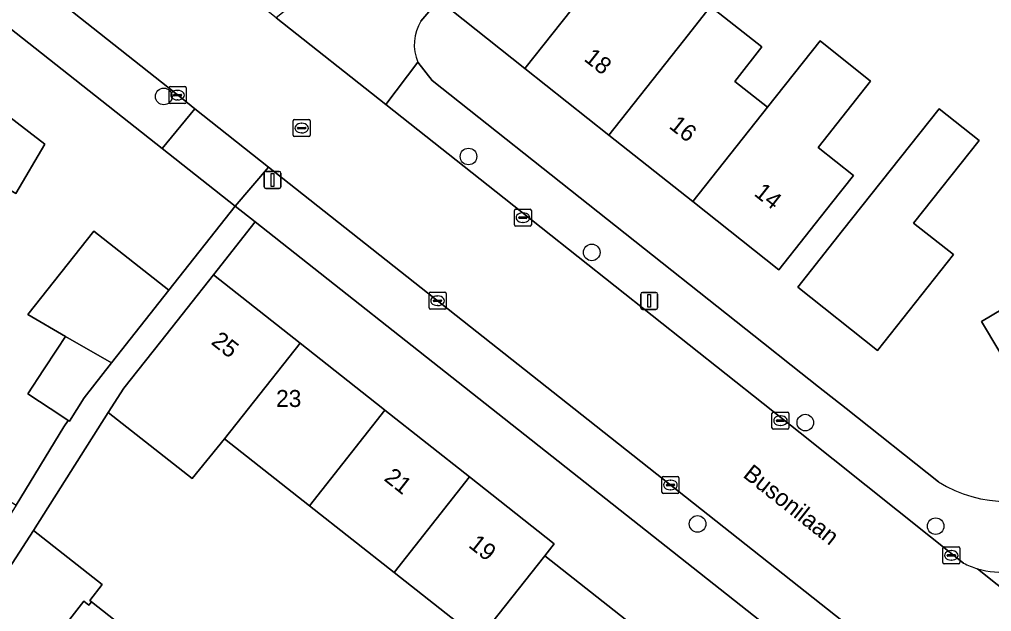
# Model space of a CAD drawing. Extents: x 159217 to 160349, y 381246 to 382172.
# Drawn here: x 160138.1 to 160195.3, y 381988.1 to 382022.9 of the extents above; entities that cross this region are included whole.
import ezdxf

# ---------------------------------------------------------------- set-up
doc = ezdxf.new("R2010")
doc.units = 0
for name, color, linetype in [('IMGEO_Boom', 7, 'Continuous'), ('IMGEO_Erf', 7, 'Continuous'), ('IMGEO_Kolk', 7, 'Continuous'), ('IMGEO_Lichtmast', 7, 'Continuous'), ('IMGEO_Muur', 7, 'Continuous'), ('IMGEO_Openbare_ruimte_label', 7, 'Continuous'), ('IMGEO_Pand', 7, 'Continuous'), ('IMGEO_Pand_nummerreeks', 7, 'Continuous'), ('IMGEO_Rijbaan_lokaal_open', 7, 'Continuous'), ('IMGEO_Rioolput', 7, 'Continuous'), ('IMGEO_Voetpad_open', 7, 'Continuous')]:
    doc.layers.add(name, color=color, linetype=linetype)

msp = doc.modelspace()

# ---------------------------------------------------------------- linework, layer by layer
at = {"layer": 'IMGEO_Boom'}
for centre in [(160146.591, 382018.373), (160164.533, 382014.84), (160171.786, 382009.194), (160184.362, 381999.177), (160178.018, 381993.215), (160192.036, 381993.082)]:
    msp.add_circle(centre, 0.489, dxfattribs=at)
at = {"layer": 'IMGEO_Erf'}
for points in [[(160135.459, 381995.859), (160137.912, 381994.317), (160140.717, 381998.927), (160140.962, 381999.311), (160140.583, 381999.559), (160138.586, 382000.866), (160139.517, 382002.28), (160140.314, 382003.49), (160140.816, 382004.253), (160138.582, 382005.534), (160142.466, 382010.454), (160146.885, 382006.965), (160150.798, 382011.919), (160146.492, 382015.319), (160130.774, 382027.732)], [(160178.788, 382023.674), (160181.806, 382021.284), (160180.205, 382019.262), (160182.135, 382017.733), (160185.23, 382021.639), (160188.206, 382019.282), (160185.111, 382015.376), (160187.203, 382013.719), (160185.91, 382012.087), (160182.805, 382008.168), (160177.738, 382012.183), (160172.79, 382016.103), (160167.842, 382020.023), (160162.777, 382024.035), (160161.732, 382022.812)], [(160233.929, 382018.543), (160233.082, 382019.946), (160225.46, 382015.406), (160220.047, 382012.182), (160214.635, 382008.958), (160209.222, 382005.734), (160203.81, 382002.51), (160199.595, 382000), (160198.272, 381999.212), (160197.801, 382000), (160194.739, 382005.121), (160199.034, 382007.682), (160200.285, 382008.428), (160199.136, 382010.356), (160199.038, 382010.521), (160198.981, 382010.617), (160204.393, 382013.84), (160207.546, 382015.718), (160208.848, 382013.532), (160211.108, 382014.879), (160209.911, 382016.888), (160215.324, 382020.112), (160216.519, 382018.105), (160221.931, 382021.33)], [(160161.552, 382020.389), (160162.394, 382019.303), (160181.902, 382003.848), (160183.535, 382002.554), (160185.145, 382001.278), (160186.758, 382000), (160192.196, 381995.692)], [(160164.507, 381986.918), (160160.15, 381990.354), (160155.165, 381994.285), (160150.177, 381998.219), (160148.267, 381995.88), (160143.327, 381999.776), (160138.933, 381992.828), (160142.971, 381989.64), (160142.24, 381988.714), (160142.347, 381988.629), (160147.34, 381984.688)]]:
    msp.add_lwpolyline(points, dxfattribs=at)
for points in [[(160118.255, 381987.024), (160117.408, 381985.582), (160114.88, 381981.268), (160107.512, 381985.605), (160110.881, 381991.35), (160114.176, 381996.967), (160115.955, 382000), (160117.471, 382002.584), (160120.765, 382008.2), (160124.08, 382013.852), (160127.432, 382019.567), (160131.914, 382016.929), (160133.752, 382020.052), (160139.591, 382015.557), (160137.882, 382012.653), (160134.482, 382014.654), (160131.509, 382009.591), (160128.149, 382003.87), (160125.876, 382000), (160124.851, 381998.255), (160121.553, 381992.64)], [(160194.59, 382015.784), (160190.739, 382010.925), (160193.088, 382009.064), (160188.616, 382003.421), (160183.914, 382007.147), (160186.553, 382010.478), (160192.236, 382017.65)], [(160165.891, 382000), (160151.974, 382010.99), (160149.511, 382007.871), (160154.615, 382003.845), (160159.491, 382000), (160159.601, 381999.913), (160164.588, 381995.98), (160169.581, 381992.043), (160169.028, 381991.343), (160174.123, 381987.314), (160179.51, 381983.054), (160182.521, 381986.867)]]:
    msp.add_lwpolyline(points, close=True, dxfattribs=at)
for centre, radius, start, end in [((160164, 382021.425), 2.659, 148.5615, 202.9414), ((160196.232, 382002.153), 7.618, 238.008, 302.3452)]:
    msp.add_arc(centre, radius, start, end, dxfattribs=at)
at = {"layer": 'IMGEO_Kolk'}
for p, q in [((160146.904, 382018.026), (160146.904, 382018.878)), ((160146.979, 382018.952), (160147.831, 382018.952)), ((160147.392, 382018.732), (160147.417, 382018.732)), ((160147.905, 382018.878), (160147.905, 382018.026)), ((160147.163, 382018.446), (160147.163, 382018.458)), ((160147.601, 382018.409), (160147.203, 382018.409)), ((160147.206, 382018.495), (160147.604, 382018.495)), ((160147.415, 382018.172), (160147.39, 382018.172)), ((160147.647, 382018.458), (160147.647, 382018.446)), ((160147.831, 382017.952), (160146.979, 382017.952)), ((160167.233, 382010.816), (160167.233, 382011.668)), ((160167.308, 382011.742), (160168.16, 382011.742)), ((160168.234, 382011.668), (160168.234, 382010.816)), ((160167.492, 382011.236), (160167.492, 382011.248)), ((160167.93, 382011.199), (160167.532, 382011.199)), ((160167.535, 382011.285), (160167.933, 382011.285)), ((160167.721, 382011.522), (160167.746, 382011.522)), ((160167.976, 382011.248), (160167.976, 382011.236)), ((160168.16, 382010.742), (160167.308, 382010.742)), ((160167.744, 382010.962), (160167.719, 382010.962)), ((160162.21, 382005.923), (160162.21, 382006.775)), ((160162.285, 382006.849), (160163.137, 382006.849)), ((160162.698, 382006.629), (160162.723, 382006.629)), ((160163.211, 382006.775), (160163.211, 382005.923)), ((160162.469, 382006.343), (160162.469, 382006.355)), ((160162.907, 382006.306), (160162.509, 382006.306)), ((160162.512, 382006.392), (160162.91, 382006.392)), ((160162.721, 382006.069), (160162.696, 382006.069)), ((160162.953, 382006.355), (160162.953, 382006.343)), ((160163.137, 382005.849), (160162.285, 382005.849)), ((160182.399, 381998.864), (160182.399, 381999.716)), ((160182.474, 381999.79), (160183.326, 381999.79)), ((160183.4, 381999.716), (160183.4, 381998.864)), ((160182.658, 381999.284), (160182.658, 381999.296)), ((160183.096, 381999.247), (160182.698, 381999.247)), ((160182.701, 381999.333), (160183.099, 381999.333)), ((160182.887, 381999.57), (160182.912, 381999.57)), ((160183.142, 381999.296), (160183.142, 381999.284)), ((160183.326, 381998.79), (160182.474, 381998.79)), ((160182.91, 381999.01), (160182.885, 381999.01)), ((160175.922, 381995.079), (160175.922, 381995.931)), ((160175.997, 381996.005), (160176.849, 381996.005)), ((160176.41, 381995.785), (160176.435, 381995.785)), ((160176.923, 381995.931), (160176.923, 381995.079)), ((160176.181, 381995.499), (160176.181, 381995.511)), ((160176.619, 381995.462), (160176.221, 381995.462)), ((160176.224, 381995.548), (160176.622, 381995.548)), ((160176.433, 381995.225), (160176.408, 381995.225)), ((160176.665, 381995.511), (160176.665, 381995.499)), ((160176.849, 381995.005), (160175.997, 381995.005)), ((160192.458, 381990.936), (160192.458, 381991.788)), ((160192.533, 381991.862), (160193.385, 381991.862)), ((160192.946, 381991.642), (160192.971, 381991.642)), ((160193.459, 381991.788), (160193.459, 381990.936)), ((160192.717, 381991.356), (160192.717, 381991.368)), ((160193.155, 381991.319), (160192.757, 381991.319)), ((160192.76, 381991.405), (160193.158, 381991.405)), ((160192.969, 381991.082), (160192.944, 381991.082)), ((160193.201, 381991.368), (160193.201, 381991.356)), ((160193.385, 381990.862), (160192.533, 381990.862))]:
    msp.add_line(p, q, dxfattribs=at)
for points in [[(160146.904, 382018.026), (160146.904, 382018.878)], [(160146.979, 382018.952), (160147.831, 382018.952)], [(160147.905, 382018.878), (160147.905, 382018.026)], [(160147.831, 382017.952), (160146.979, 382017.952)], [(160167.233, 382010.816), (160167.233, 382011.668)], [(160167.308, 382011.742), (160168.16, 382011.742)], [(160168.234, 382011.668), (160168.234, 382010.816)], [(160168.16, 382010.742), (160167.308, 382010.742)], [(160162.21, 382005.923), (160162.21, 382006.775)], [(160162.285, 382006.849), (160163.137, 382006.849)], [(160163.211, 382006.775), (160163.211, 382005.923)], [(160163.137, 382005.849), (160162.285, 382005.849)], [(160182.399, 381998.864), (160182.399, 381999.716)], [(160182.474, 381999.79), (160183.326, 381999.79)], [(160183.4, 381999.716), (160183.4, 381998.864)], [(160183.326, 381998.79), (160182.474, 381998.79)], [(160175.922, 381995.079), (160175.922, 381995.931)], [(160175.997, 381996.005), (160176.849, 381996.005)], [(160176.923, 381995.931), (160176.923, 381995.079)], [(160176.849, 381995.005), (160175.997, 381995.005)], [(160192.458, 381990.936), (160192.458, 381991.788)], [(160192.533, 381991.862), (160193.385, 381991.862)], [(160193.459, 381991.788), (160193.459, 381990.936)], [(160193.385, 381990.862), (160192.533, 381990.862)]]:
    msp.add_lwpolyline(points, dxfattribs=at)
for centre, radius, start, end in [((160146.981, 382018.876), 0.0765, 91.552, 178.448), ((160146.981, 382018.876), 0.0765, 91.552, 178.448), ((160147.829, 382018.876), 0.0765, 1.552, 88.448), ((160147.829, 382018.876), 0.0765, 1.552, 88.448), ((160146.981, 382018.028), 0.0765, 181.552, 268.448), ((160146.981, 382018.028), 0.0765, 181.552, 268.448), ((160147.203, 382018.455), 0.0403, 85.8775, 175.7526), ((160147.2, 382018.445), 0.0366, 178.938, 274.7102), ((160147.604, 382018.452), 0.043, 264.8664, 352.4533), ((160147.608, 382018.457), 0.0386, 1.7309, 96.639), ((160147.829, 382018.028), 0.0765, 271.552, 358.448), ((160147.829, 382018.028), 0.0765, 271.552, 358.448), ((160167.31, 382011.666), 0.0765, 91.552, 178.448), ((160167.31, 382011.666), 0.0765, 91.552, 178.448), ((160168.158, 382011.666), 0.0765, 1.552, 88.448), ((160168.158, 382011.666), 0.0765, 1.552, 88.448), ((160167.532, 382011.245), 0.0403, 85.8775, 175.7526), ((160167.529, 382011.235), 0.0366, 178.938, 274.7102), ((160167.933, 382011.242), 0.043, 264.8664, 352.4533), ((160167.937, 382011.247), 0.0386, 1.7309, 96.639), ((160167.31, 382010.818), 0.0765, 181.552, 268.448), ((160167.31, 382010.818), 0.0765, 181.552, 268.448), ((160168.158, 382010.818), 0.0765, 271.552, 358.448), ((160168.158, 382010.818), 0.0765, 271.552, 358.448), ((160162.287, 382006.773), 0.0765, 91.552, 178.448), ((160162.287, 382006.773), 0.0765, 91.552, 178.448), ((160163.135, 382006.773), 0.0765, 1.552, 88.448), ((160163.135, 382006.773), 0.0765, 1.552, 88.448), ((160162.509, 382006.352), 0.0403, 85.8775, 175.7526), ((160162.506, 382006.342), 0.0366, 178.938, 274.7102), ((160162.91, 382006.349), 0.043, 264.8664, 352.4533), ((160162.914, 382006.354), 0.0386, 1.7309, 96.639), ((160162.287, 382005.925), 0.0765, 181.552, 268.448), ((160162.287, 382005.925), 0.0765, 181.552, 268.448), ((160163.135, 382005.925), 0.0765, 271.552, 358.448), ((160163.135, 382005.925), 0.0765, 271.552, 358.448), ((160182.476, 381999.714), 0.0765, 91.552, 178.448), ((160182.476, 381999.714), 0.0765, 91.552, 178.448), ((160183.324, 381999.714), 0.0765, 1.552, 88.448), ((160183.324, 381999.714), 0.0765, 1.552, 88.448), ((160182.698, 381999.293), 0.0403, 85.8775, 175.7526), ((160182.695, 381999.283), 0.0366, 178.938, 274.7102), ((160183.099, 381999.29), 0.043, 264.8664, 352.4533), ((160183.103, 381999.295), 0.0386, 1.7309, 96.639), ((160182.476, 381998.866), 0.0765, 181.552, 268.448), ((160182.476, 381998.866), 0.0765, 181.552, 268.448), ((160183.324, 381998.866), 0.0765, 271.552, 358.448), ((160183.324, 381998.866), 0.0765, 271.552, 358.448), ((160175.999, 381995.929), 0.0765, 91.552, 178.448), ((160175.999, 381995.929), 0.0765, 91.552, 178.448), ((160176.847, 381995.929), 0.0765, 1.552, 88.448), ((160176.847, 381995.929), 0.0765, 1.552, 88.448), ((160175.999, 381995.081), 0.0765, 181.552, 268.448), ((160175.999, 381995.081), 0.0765, 181.552, 268.448), ((160176.221, 381995.508), 0.0403, 85.8775, 175.7526), ((160176.218, 381995.498), 0.0366, 178.938, 274.7102), ((160176.622, 381995.505), 0.043, 264.8664, 352.4533), ((160176.626, 381995.51), 0.0386, 1.7309, 96.639), ((160176.847, 381995.081), 0.0765, 271.552, 358.448), ((160176.847, 381995.081), 0.0765, 271.552, 358.448), ((160192.535, 381991.786), 0.0765, 91.552, 178.448), ((160192.535, 381991.786), 0.0765, 91.552, 178.448), ((160193.383, 381991.786), 0.0765, 1.552, 88.448), ((160193.383, 381991.786), 0.0765, 1.552, 88.448), ((160192.757, 381991.365), 0.0403, 85.8775, 175.7526), ((160192.754, 381991.355), 0.0366, 178.938, 274.7102), ((160193.158, 381991.362), 0.043, 264.8664, 352.4533), ((160193.162, 381991.367), 0.0386, 1.7309, 96.639), ((160192.535, 381990.938), 0.0765, 181.552, 268.448), ((160192.535, 381990.938), 0.0765, 181.552, 268.448), ((160193.383, 381990.938), 0.0765, 271.552, 358.448), ((160193.383, 381990.938), 0.0765, 271.552, 358.448)]:
    msp.add_arc(centre, radius, start, end, dxfattribs=at)
for centre, major_axis, ratio, start_param, end_param in [((160147.391, 382018.452), (-0.387, 0.002), 0.722429, 4.712389, 7.853982), ((160147.416, 382018.452), (-0.39, 0.002), 0.717154, 1.570796, 4.712389), ((160167.72, 382011.242), (-0.387, 0.002), 0.722429, 4.712389, 7.853982), ((160167.745, 382011.242), (-0.39, 0.002), 0.717154, 1.570796, 4.712389), ((160162.697, 382006.349), (-0.387, 0.002), 0.722429, 4.712389, 7.853982), ((160162.722, 382006.349), (-0.39, 0.002), 0.717154, 1.570796, 4.712389), ((160182.886, 381999.29), (-0.387, 0.002), 0.722429, 4.712389, 7.853982), ((160182.911, 381999.29), (-0.39, 0.002), 0.717154, 1.570796, 4.712389), ((160176.409, 381995.505), (-0.387, 0.002), 0.722429, 4.712389, 7.853982), ((160176.434, 381995.505), (-0.39, 0.002), 0.717154, 1.570796, 4.712389), ((160192.945, 381991.362), (-0.387, 0.002), 0.722429, 4.712389, 7.853982), ((160192.97, 381991.362), (-0.39, 0.002), 0.717154, 1.570796, 4.712389)]:
    msp.add_ellipse(centre, major_axis=major_axis, ratio=ratio, start_param=start_param, end_param=end_param, dxfattribs=at)
at = {"layer": 'IMGEO_Lichtmast'}
for p, q in [((160152.603, 382013.957), (160153.393, 382013.957)), ((160153.393, 382013.957), (160152.603, 382013.957)), ((160152.503, 382013.057), (160152.503, 382013.857)), ((160152.503, 382013.857), (160152.503, 382013.057)), ((160153.493, 382013.857), (160153.493, 382013.057)), ((160153.493, 382013.057), (160153.493, 382013.857)), ((160153.393, 382012.957), (160152.603, 382012.957)), ((160152.603, 382012.957), (160153.393, 382012.957)), ((160174.673, 382005.938), (160174.673, 382006.738)), ((160174.673, 382006.738), (160174.673, 382005.938)), ((160174.773, 382006.838), (160175.563, 382006.838)), ((160175.563, 382006.838), (160174.773, 382006.838)), ((160175.663, 382006.738), (160175.663, 382005.938)), ((160175.663, 382005.938), (160175.663, 382006.738)), ((160175.563, 382005.838), (160174.773, 382005.838)), ((160174.773, 382005.838), (160175.563, 382005.838))]:
    msp.add_line(p, q, dxfattribs=at)
for points in [[(160152.923, 382013.832), (160153.073, 382013.832), (160153.073, 382013.082), (160152.923, 382013.082), (160152.923, 382013.832)], [(160175.093, 382006.713), (160175.243, 382006.713), (160175.243, 382005.963), (160175.093, 382005.963), (160175.093, 382006.713)]]:
    msp.add_lwpolyline(points, dxfattribs=at)
for centre, start, end in [((160152.603, 382013.857), 90, 180), ((160152.603, 382013.857), 90, 180), ((160153.393, 382013.857), 0, 90), ((160153.393, 382013.857), 360, 90), ((160152.603, 382013.057), 180, 270), ((160152.603, 382013.057), 180, 270), ((160153.393, 382013.057), 270, 0), ((160153.393, 382013.057), 270, 0), ((160174.773, 382006.738), 90, 180), ((160174.773, 382006.738), 90, 180), ((160175.563, 382006.738), 0, 90), ((160175.563, 382006.738), 360, 90), ((160174.773, 382005.938), 180, 270), ((160174.773, 382005.938), 180, 270), ((160175.563, 382005.938), 270, 0), ((160175.563, 382005.938), 270, 0)]:
    msp.add_arc(centre, 0.1, start, end, dxfattribs=at)
at = {"layer": 'IMGEO_Muur'}
msp.add_lwpolyline([(160181.902, 382003.848), (160183.535, 382002.554), (160185.145, 382001.278), (160186.758, 382000), (160192.196, 381995.692)], dxfattribs=at)
at = {"layer": 'IMGEO_Pand'}
for points in [[(160174.443, 382028.355), (160172.155, 382030.167), (160169.951, 382027.385), (160167.174, 382029.585), (160165.183, 382027.072), (160162.777, 382024.035), (160167.842, 382020.023), (160172.238, 382025.573)], [(160178.788, 382023.674), (160179.392, 382024.435), (160177.204, 382026.169), (160174.443, 382028.355), (160172.238, 382025.573), (160167.842, 382020.023), (160172.79, 382016.103), (160177.187, 382021.653)], [(160182.135, 382017.733), (160180.205, 382019.262), (160181.806, 382021.284), (160178.788, 382023.674), (160177.187, 382021.653), (160172.79, 382016.103), (160177.738, 382012.183)], [(160182.135, 382017.733), (160177.738, 382012.183), (160182.805, 382008.168), (160185.91, 382012.087), (160187.203, 382013.719), (160185.111, 382015.376), (160188.206, 382019.282), (160185.23, 382021.639)], [(160124.08, 382013.852), (160131.509, 382009.591), (160134.482, 382014.654), (160137.882, 382012.653), (160139.591, 382015.557), (160133.752, 382020.052), (160131.914, 382016.929), (160127.432, 382019.567)], [(160190.739, 382010.925), (160194.59, 382015.784), (160192.236, 382017.65), (160186.553, 382010.478), (160183.914, 382007.147), (160188.616, 382003.421), (160193.088, 382009.064)], [(160146.885, 382006.965), (160142.466, 382010.454), (160138.582, 382005.534), (160140.816, 382004.253), (160143.525, 382002.699)], [(160200.285, 382008.428), (160199.034, 382007.682), (160194.739, 382005.121), (160197.801, 382000), (160198.272, 381999.212), (160199.595, 382000), (160203.81, 382002.51)], [(160150.177, 381998.219), (160151.583, 382000), (160154.615, 382003.845), (160149.511, 382007.871), (160146.413, 382003.947), (160145.07, 382002.247), (160144.25, 382001.198), (160143.327, 381999.776), (160148.267, 381995.88)], [(160143.525, 382002.699), (160140.816, 382004.253), (160140.314, 382003.49), (160139.517, 382002.28), (160138.586, 382000.866), (160140.583, 381999.559), (160140.962, 381999.311), (160141.034, 381999.264), (160141.907, 382000.644)], [(160155.165, 381994.285), (160159.601, 381999.913), (160159.491, 382000), (160154.615, 382003.845), (160151.583, 382000), (160150.177, 381998.219)], [(160155.165, 381994.285), (160160.15, 381990.354), (160164.588, 381995.98), (160159.601, 381999.913)], [(160169.028, 381991.343), (160169.581, 381992.043), (160164.588, 381995.98), (160160.15, 381990.354), (160164.507, 381986.918), (160164.969, 381986.553), (160165.135, 381986.422)], [(160140.263, 381985.397), (160141.368, 381986.793), (160140.78, 381987.259), (160141.89, 381988.662), (160142.184, 381988.429), (160142.347, 381988.629), (160142.24, 381988.714), (160142.971, 381989.64), (160138.933, 381992.828), (160136.182, 381988.616)], [(160174.123, 381987.314), (160169.028, 381991.343), (160165.135, 381986.422), (160167.672, 381984.421), (160167.101, 381983.7), (160166.815, 381983.338), (160166.233, 381982.602), (160165.503, 381983.179), (160161.547, 381978.176), (160164.601, 381975.761), (160164.645, 381975.726), (160166.802, 381978.285), (160167.256, 381978.823), (160167.38, 381978.971), (160169.661, 381981.676), (160170.234, 381982.4)], [(160140.263, 381985.397), (160144.969, 381981.684), (160147.34, 381984.688), (160142.347, 381988.629), (160142.184, 381988.429), (160141.89, 381988.662), (160140.78, 381987.259), (160141.368, 381986.793)]]:
    msp.add_lwpolyline(points, close=True, dxfattribs=at)
at = {"layer": 'IMGEO_Rijbaan_lokaal_open'}
for points in [[(160193.666, 381990.913), (160184.067, 381998.574), (160166.634, 382012.378), (160159.669, 382017.89), (160153.216, 382022.998), (160137.206, 382035.701), (160135.457, 382037.171)], [(160132.773, 382030.024), (160147.666, 382018.247), (160148.418, 382017.652), (160152.766, 382014.214), (160170.741, 382000), (160222.676, 381958.931)], [(160205.117, 381982.119), (160194.495, 381990.58)], [(160194.495, 381990.58), (160205.117, 381982.119)]]:
    msp.add_lwpolyline(points, dxfattribs=at)
for centre, radius, start, end in [((160195.853, 381995.155), 4.772, 253.4732, 302.4058), ((160195.857, 381995.168), 4.786, 242.76, 253.4704)]:
    msp.add_arc(centre, radius, start, end, dxfattribs=at)
at = {"layer": 'IMGEO_Rioolput'}
for p, q in [((160154.21, 382016.086), (160154.21, 382016.938)), ((160154.285, 382017.012), (160155.137, 382017.012)), ((160155.211, 382016.938), (160155.211, 382016.086)), ((160154.469, 382016.506), (160154.469, 382016.518)), ((160154.907, 382016.469), (160154.509, 382016.469)), ((160154.512, 382016.555), (160154.91, 382016.555)), ((160154.698, 382016.792), (160154.723, 382016.792)), ((160154.953, 382016.518), (160154.953, 382016.506)), ((160155.137, 382016.012), (160154.285, 382016.012)), ((160154.721, 382016.232), (160154.696, 382016.232))]:
    msp.add_line(p, q, dxfattribs=at)
for points in [[(160154.21, 382016.086), (160154.21, 382016.938)], [(160154.285, 382017.012), (160155.137, 382017.012)], [(160155.211, 382016.938), (160155.211, 382016.086)], [(160155.137, 382016.012), (160154.285, 382016.012)]]:
    msp.add_lwpolyline(points, dxfattribs=at)
for centre, radius, start, end in [((160154.287, 382016.936), 0.0765, 91.552, 178.448), ((160154.287, 382016.936), 0.0765, 91.552, 178.448), ((160155.135, 382016.936), 0.0765, 1.552, 88.448), ((160155.135, 382016.936), 0.0765, 1.552, 88.448), ((160154.509, 382016.515), 0.0403, 85.8775, 175.7526), ((160154.506, 382016.505), 0.0366, 178.938, 274.7102), ((160154.91, 382016.512), 0.043, 264.8664, 352.4533), ((160154.914, 382016.517), 0.0386, 1.7309, 96.639), ((160154.287, 382016.088), 0.0765, 181.552, 268.448), ((160154.287, 382016.088), 0.0765, 181.552, 268.448), ((160155.135, 382016.088), 0.0765, 271.552, 358.448), ((160155.135, 382016.088), 0.0765, 271.552, 358.448)]:
    msp.add_arc(centre, radius, start, end, dxfattribs=at)
for centre, major_axis, ratio, start_param, end_param in [((160154.697, 382016.512), (-0.387, 0.002), 0.722429, 4.712389, 7.853982), ((160154.722, 382016.512), (-0.39, 0.002), 0.717154, 1.570796, 4.712389)]:
    msp.add_ellipse(centre, major_axis=major_axis, ratio=ratio, start_param=start_param, end_param=end_param, dxfattribs=at)
at = {"layer": 'IMGEO_Voetpad_open'}
for points in [[(160127.222, 382030.546), (160130.774, 382027.732), (160146.492, 382015.319), (160148.418, 382017.652), (160147.666, 382018.247), (160132.773, 382030.024)], [(160165.183, 382027.072), (160159.659, 382030.345), (160158.778, 382028.852), (160157.025, 382026.062), (160153.216, 382022.998), (160159.669, 382017.89), (160161.552, 382020.389)], [(160161.732, 382022.812), (160162.777, 382024.035), (160165.183, 382027.072)], [(160162.394, 382019.303), (160161.552, 382020.389), (160159.669, 382017.89), (160166.634, 382012.378), (160184.067, 381998.574), (160193.666, 381990.913)], [(160192.196, 381995.692), (160186.758, 382000), (160185.145, 382001.278), (160183.535, 382002.554), (160181.902, 382003.848), (160162.394, 382019.303)], [(160222.676, 381958.931), (160170.741, 382000), (160152.766, 382014.214), (160150.798, 382011.919), (160151.974, 382010.99), (160165.891, 382000), (160182.521, 381986.867), (160184.467, 381985.33), (160219.656, 381957.541)], [(160140.263, 381985.397), (160136.182, 381988.616), (160138.933, 381992.828), (160143.327, 381999.776), (160144.25, 382001.198), (160145.07, 382002.247), (160146.413, 382003.947), (160149.511, 382007.871), (160151.974, 382010.99), (160150.798, 382011.919), (160146.885, 382006.965), (160143.525, 382002.699), (160141.907, 382000.644), (160141.034, 381999.264), (160140.962, 381999.311), (160140.717, 381998.927), (160137.912, 381994.317), (160136.201, 381991.597), (160134.467, 381988.841), (160134.234, 381988.47), (160128.915, 381980.458)]]:
    msp.add_lwpolyline(points, dxfattribs=at)
msp.add_lwpolyline([(160148.418, 382017.652), (160146.492, 382015.319), (160150.798, 382011.919), (160152.766, 382014.214)], close=True, dxfattribs=at)
for centre, radius, start, end in [((160164, 382021.425), 2.659, 148.5615, 202.9414), ((160196.232, 382002.153), 7.618, 238.008, 302.3452), ((160195.853, 381995.155), 4.772, 253.4732, 302.4058), ((160195.857, 381995.168), 4.786, 242.76, 253.4704)]:
    msp.add_arc(centre, radius, start, end, dxfattribs=at)

# ---------------------------------------------------------------- texts
at = {"layer": 'IMGEO_Openbare_ruimte_label'}
msp.add_text('Busonilaan', height=1, rotation=321.6625, dxfattribs=at).set_placement((160180.637, 381996.01))
at = {"layer": 'IMGEO_Pand_nummerreeks'}
for s, rotation, p in [('18', 321.6118, (160171.277, 382020.516)), ('16', 321.6118, (160176.282, 382016.551)), ('14', 321.6123, (160181.29, 382012.583)), ('25', 321.7393, (160149.325, 382003.84)), ('21', 321.7406, (160159.505, 381995.812)), ('19', 321.7379, (160164.477, 381991.889))]:
    msp.add_text(s, height=1, rotation=rotation, dxfattribs=at).set_placement(p)
msp.add_text('23', height=1, dxfattribs=at).set_placement((160153.204, 382000.097))

doc.saveas('drawing.dxf')
